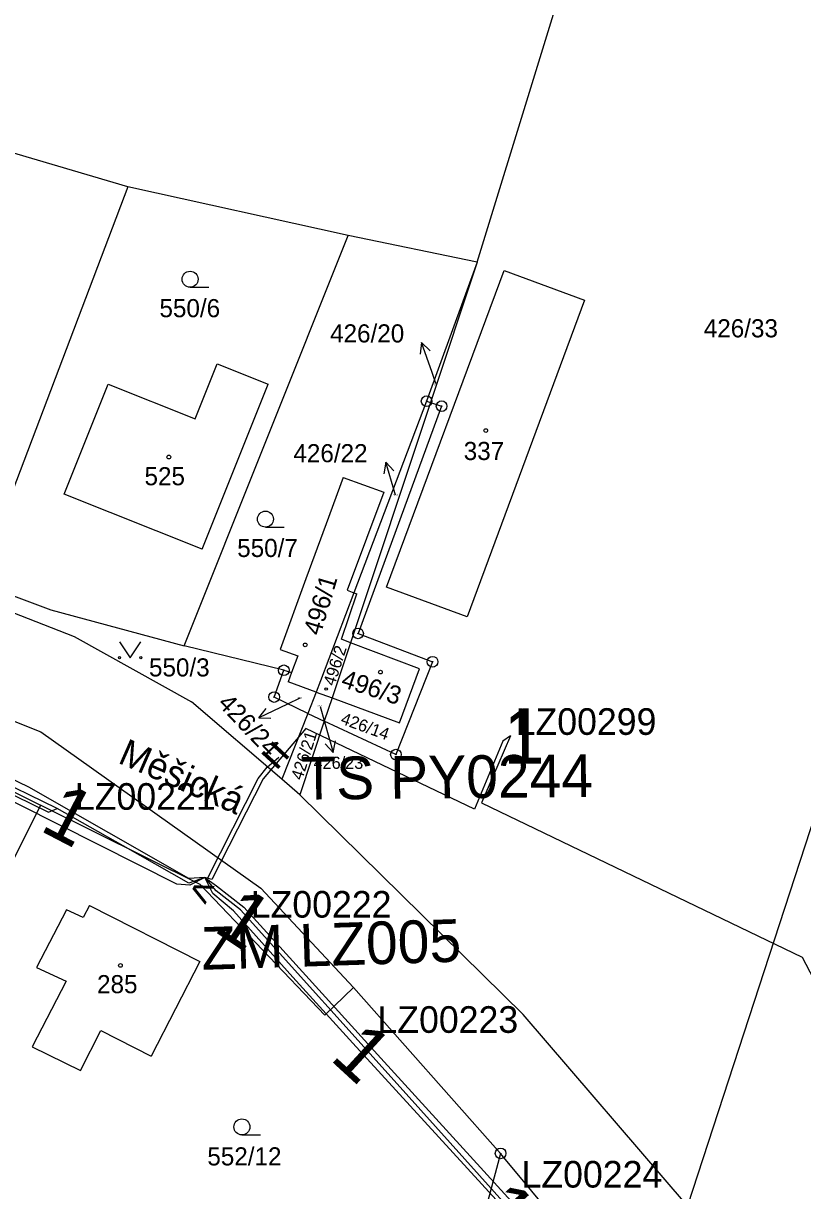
# Model space of a CAD drawing. Extents: x -738131 to -734179, y -1033447 to -1030078.
# Drawn here: x -735722 to -735648.9, y -1031900.8 to -1031791.3 of the extents above; entities that cross this region are included whole.
import ezdxf

# ---------------------------------------------------------------- set-up
doc = ezdxf.new("R2010")
doc.units = 0
for name, color, linetype in [('ftf_2010', 7, 'Continuous'), ('ftf_2060', 7, 'Continuous'), ('ftf_3010', 7, 'Continuous'), ('ftf_3010_ftf_3010_gtda_3015_gtda_3015_1', 7, 'Continuous'), ('ftf_3150', 7, 'Continuous'), ('ftf_3150_ftf_3150_gtda_3155_gtda_3155_1', 7, 'Continuous'), ('ftf_3160', 7, 'Continuous'), ('ftf_3160_ftf_3160_gtda_3165_gtda_3165_1', 7, 'Continuous'), ('ftf_nu', 7, 'Continuous'), ('Vrstva 1', 7, 'Continuous'), ('Vrstva 2', 7, 'Continuous'), ('Vrstva 3', 7, 'Continuous'), ('Vrstva 5', 7, 'Continuous'), ('Vrstva 7', 7, 'Continuous'), ('Vrstva 8', 7, 'Continuous')]:
    doc.layers.add(name, color=color, linetype=linetype)

msp = doc.modelspace()

# ---------------------------------------------------------------- linework, layer by layer
at = {"layer": 'ftf_2010'}
for points in [[(-735704.95, -1031871.47), (-735706.47, -1031871.55), (-735713.97, -1031867.28), (-735721.47, -1031863), (-735735.75, -1031856.08), (-735750.03, -1031849.16), (-735751.26, -1031849.34), (-735759.78, -1031845.67), (-735767.94, -1031842.11), (-735768.8, -1031841.74), (-735782.82, -1031840.2), (-735802.7, -1031839.67), (-735840.4, -1031839.84), (-735851.45, -1031845.21), (-735851.86, -1031848.34)], [(-735767.65, -1031843.06), (-735750.47, -1031850.23), (-735719.61, -1031865.34), (-735718.8, -1031864.98)], [(-735704.95, -1031871.47), (-735706.37, -1031872.19), (-735707.6, -1031872.09), (-735722.28, -1031864.67), (-735736.96, -1031857.25), (-735750.81, -1031850.37), (-735752.37, -1031850.93), (-735752.89, -1031850.37), (-735752.83, -1031849.61), (-735766.65, -1031843.74), (-735764.94, -1031846.69), (-735783.41, -1031916.56), (-735791.12, -1031947.31)], [(-735718.8, -1031864.98), (-735738.44, -1031855.43)], [(-735676.31, -1031858.18), (-735677.01, -1031858.66), (-735679.67, -1031865.06), (-735695.5, -1031857.49), (-735699.51, -1031862.2), (-735704.31, -1031871.66), (-735704.95, -1031871.47)], [(-735676.31, -1031858.18), (-735677.49, -1031860.92), (-735679.01, -1031864.47), (-735648.94, -1031878.95), (-735643.98, -1031888.46), (-735640.63, -1031888.9), (-735640.19, -1031889.82), (-735640.21, -1031890.18), (-735639.83, -1031890.32), (-735639.52, -1031890.34), (-735631.26, -1031887.06)], [(-735704.95, -1031871.47), (-735706.46, -1031871.99), (-735712.63, -1031868.48), (-735718.8, -1031864.98)], [(-735661.74, -1031918.22), (-735675.07, -1031904.03), (-735686.1, -1031891.76), (-735701.63, -1031874.49), (-735703.91, -1031872.73), (-735704.95, -1031871.47)], [(-735702.29, -1031874.6), (-735704.22, -1031872.98), (-735704.95, -1031871.47)], [(-735704.95, -1031871.47), (-735703.88, -1031872.24), (-735701.31, -1031874.26), (-735688.46, -1031888.4), (-735675.6, -1031902.54), (-735685.91, -1031938.23), (-735694.04, -1031973.11), (-735694.47, -1031973.74)], [(-735691.1, -1031887), (-735696.7, -1031880.8), (-735702.29, -1031874.6)], [(-735677.66, -1031901.72), (-735691.1, -1031887)]]:
    msp.add_lwpolyline(points, dxfattribs=at)
at = {"layer": 'ftf_2060'}
msp.add_lwpolyline([(-735704.95, -1031871.47), (-735704.67, -1031871.48), (-735699.95, -1031862.18), (-735699.11, -1031861.1), (-735698.04, -1031860.18)], dxfattribs=at)
at = {"layer": 'Vrstva 1'}
for points in [[(-735679.43, -1031813.72), (-735657.43, -1031742.17)], [(-735712.17, -1031806.65), (-735732.96, -1031800.52)], [(-735712.17, -1031806.65), (-735726.29, -1031843.79)], [(-735691.54, -1031811.21), (-735712.17, -1031806.65)], [(-735706.89, -1031849.74), (-735691.54, -1031811.21)], [(-735679.43, -1031813.72), (-735691.54, -1031811.21)], [(-735687.93, -1031844.21), (-735676.91, -1031814.51)], [(-735679.43, -1031813.72), (-735684.17, -1031826.77)], [(-735679.43, -1031813.72), (-735683.81, -1031826.89)], [(-735676.91, -1031814.51), (-735669.35, -1031817.28)], [(-735631.46, -1031815.6), (-735659.7, -1031902.27)], [(-735669.35, -1031817.28), (-735680.38, -1031846.99)], [(-735705.86, -1031828.42), (-735703.81, -1031823.27)], [(-735703.81, -1031823.27), (-735699.04, -1031825.17)], [(-735718.15, -1031835.51), (-735714.02, -1031825.16)], [(-735714.02, -1031825.16), (-735705.86, -1031828.42)], [(-735705.21, -1031840.67), (-735699.04, -1031825.17)], [(-735683.81, -1031826.89), (-735691.3, -1031849.43)], [(-735684.17, -1031826.77), (-735690.98, -1031844.74)], [(-735682.76, -1031827.24), (-735690.6, -1031848.56)], [(-735684.17, -1031826.77), (-735683.81, -1031826.89)], [(-735683.81, -1031826.89), (-735682.76, -1031827.24)], [(-735759.05, -1031832.5), (-735717.21, -1031848.85)], [(-735691.99, -1031833.92), (-735693.59, -1031838.29)], [(-735691.99, -1031833.92), (-735688.17, -1031835.32)], [(-735705.21, -1031840.67), (-735718.15, -1031835.51)], [(-735688.17, -1031835.32), (-735689.8, -1031839.67)], [(-735693.59, -1031838.29), (-735695.49, -1031843.45)], [(-735689.8, -1031839.67), (-735691.61, -1031844.5)], [(-735762.15, -1031841.1), (-735720.34, -1031857.78)], [(-735726.29, -1031843.79), (-735719.39, -1031846.35)], [(-735695.49, -1031843.45), (-735697.91, -1031850.06)], [(-735680.38, -1031846.99), (-735687.93, -1031844.21)], [(-735690.98, -1031844.74), (-735694.11, -1031853.01)], [(-735692.14, -1031849.11), (-735690.71, -1031844.84)], [(-735691.61, -1031844.5), (-735690.98, -1031844.74)], [(-735690.98, -1031844.74), (-735690.71, -1031844.84)], [(-735719.39, -1031846.35), (-735706.89, -1031849.74)], [(-735690.6, -1031848.56), (-735683.61, -1031851.22)], [(-735717.21, -1031848.85), (-735706.22, -1031854.97)], [(-735697.56, -1031852.02), (-735706.89, -1031849.74)], [(-735691.3, -1031849.43), (-735693.03, -1031854.62)], [(-735691.3, -1031849.43), (-735692.14, -1031849.11)], [(-735684.85, -1031851.89), (-735691.3, -1031849.43)], [(-735697.91, -1031850.06), (-735696.25, -1031850.66)], [(-735696.25, -1031850.66), (-735696.83, -1031852.23)], [(-735683.61, -1031851.22), (-735687.04, -1031859.93)], [(-735686.72, -1031856.96), (-735684.85, -1031851.89)], [(-735698.46, -1031854.53), (-735697.56, -1031852.02)], [(-735697.56, -1031852.02), (-735696.83, -1031852.23)], [(-735696.83, -1031852.23), (-735697.14, -1031853.09)], [(-735694.11, -1031853.01), (-735694.52, -1031854.06)], [(-735694.52, -1031854.06), (-735697.14, -1031853.09)], [(-735694.52, -1031854.06), (-735695.32, -1031856.08)], [(-735694.52, -1031854.06), (-735693.03, -1031854.62)], [(-735741.08, -1031854.36), (-735720.37, -1031864.67)], [(-735697.76, -1031862.24), (-735706.22, -1031854.97)], [(-735695.32, -1031856.08), (-735698.46, -1031854.53)], [(-735693.03, -1031854.62), (-735693.76, -1031856.81)], [(-735693.03, -1031854.62), (-735686.72, -1031856.96)], [(-735695.32, -1031856.08), (-735697.76, -1031862.24)], [(-735695.32, -1031856.08), (-735693.76, -1031856.81)], [(-735693.76, -1031856.81), (-735696.05, -1031863.71)], [(-735687.04, -1031859.93), (-735693.76, -1031856.81)], [(-735720.34, -1031857.78), (-735699.72, -1031872.45)], [(-735696.05, -1031863.71), (-735697.76, -1031862.24)], [(-735696.05, -1031863.71), (-735675.11, -1031884.31)], [(-735720.37, -1031864.67), (-735734.46, -1031892.93)], [(-735705.4, -1031872.12), (-735720.37, -1031864.67)], [(-735705.4, -1031872.12), (-735693.72, -1031884.37)], [(-735691.02, -1031881.79), (-735699.72, -1031872.45)], [(-735717.94, -1031874.5), (-735720.74, -1031879.92)], [(-735716.37, -1031875.21), (-735717.94, -1031874.5)], [(-735715.78, -1031874.08), (-735716.37, -1031875.21)], [(-735715.78, -1031874.08), (-735705.42, -1031879.33)], [(-735720.74, -1031879.92), (-735717.97, -1031881.19)], [(-735705.42, -1031879.33), (-735710.01, -1031888.24)], [(-735717.97, -1031881.19), (-735721.16, -1031887.36)], [(-735693.72, -1031884.37), (-735691.02, -1031881.79)], [(-735677.23, -1031897.35), (-735691.02, -1031881.79)], [(-735659.7, -1031902.27), (-735675.11, -1031884.31)], [(-735716.62, -1031889.56), (-735714.73, -1031885.82)], [(-735714.73, -1031885.82), (-735710.01, -1031888.24)], [(-735721.16, -1031887.36), (-735716.62, -1031889.56)], [(-735677.23, -1031897.35), (-735682.83, -1031918.31)], [(-735671.35, -1031904.42), (-735677.23, -1031897.35)]]:
    msp.add_lwpolyline(points, dxfattribs=at)
at = {"layer": 'Vrstva 3'}
for p, q in [((-735706.35, -1031816.08), (-735704.6, -1031816.08)), ((-735699.28, -1031838.59), (-735697.53, -1031838.59)), ((-735701.49, -1031895.62), (-735699.74, -1031895.62))]:
    msp.add_line(p, q, dxfattribs=at)
msp.add_lwpolyline([(-735712.96, -1031849.34), (-735711.96, -1031850.84), (-735710.96, -1031849.34)], dxfattribs=at)
for centre, radius in [((-735706.35, -1031815.33), 0.75), ((-735699.28, -1031837.84), 0.75), ((-735712.96, -1031850.84), 0.1), ((-735710.96, -1031850.84), 0.1), ((-735701.49, -1031894.87), 0.75)]:
    msp.add_circle(centre, radius, dxfattribs=at)
at = {"layer": 'Vrstva 5'}
for centre, radius in [((-735678.62, -1031829.53), 0.175), ((-735708.34, -1031832.01), 0.175), ((-735695.55, -1031849.64), 0.175), ((-735688.5, -1031852.19), 0.175), ((-735693.59, -1031853.78), 0.117), ((-735712.88, -1031879.71), 0.175)]:
    msp.add_circle(centre, radius, dxfattribs=at)
at = {"layer": 'Vrstva 7'}
for p, q in [((-735684.64, -1031821.26), (-735684.78, -1031822.36)), ((-735683.65, -1031824.09), (-735684.64, -1031821.26)), ((-735684.64, -1031821.26), (-735683.84, -1031822.04)), ((-735688, -1031832.5), (-735688.19, -1031833.6)), ((-735687.14, -1031835.38), (-735688, -1031832.5)), ((-735688, -1031832.5), (-735687.23, -1031833.32)), ((-735697.2, -1031855.19), (-735699.91, -1031856.49)), ((-735699.91, -1031856.49), (-735699.22, -1031855.6)), ((-735699.91, -1031856.49), (-735698.79, -1031856.51)), ((-735693.75, -1031856.86), (-735692.93, -1031859.75)), ((-735692.93, -1031859.75), (-735693.69, -1031858.92)), ((-735692.93, -1031859.75), (-735692.72, -1031858.65))]:
    msp.add_line(p, q, dxfattribs=at)
for points in [[(-735683.3, -1031825.1), (-735683.65, -1031824.09)], [(-735687.08, -1031835.59), (-735687.14, -1031835.38)], [(-735696.05, -1031854.64), (-735697.2, -1031855.19)], [(-735694.16, -1031855.41), (-735693.75, -1031856.86)]]:
    msp.add_lwpolyline(points, dxfattribs=at)
at = {"layer": 'Vrstva 8'}
for centre, radius in [((-735684.17, -1031826.77), 0.5), ((-735684.17, -1031826.77), 0.0303), ((-735682.76, -1031827.24), 0.5), ((-735682.76, -1031827.24), 0.0303), ((-735690.6, -1031848.56), 0.5), ((-735690.6, -1031848.56), 0.0303), ((-735683.61, -1031851.22), 0.5), ((-735697.56, -1031852.02), 0.5), ((-735683.61, -1031851.22), 0.0303), ((-735697.56, -1031852.02), 0.0303), ((-735698.46, -1031854.53), 0.5), ((-735698.46, -1031854.53), 0.0303), ((-735687.04, -1031859.93), 0.5), ((-735687.04, -1031859.93), 0.0303), ((-735677.23, -1031897.35), 0.5), ((-735677.23, -1031897.35), 0.0303)]:
    msp.add_circle(centre, radius, dxfattribs=at)

# ---------------------------------------------------------------- texts
at = {"layer": 'ftf_3010'}
msp.add_text('1', height=5.2, dxfattribs=at).set_placement((-735676.96, -1031860.78))
for rotation, p in [(332.5, (-735720.57, -1031866.99)), (326.2049, (-735704.28, -1031876.4)), (317.4007, (-735693.34, -1031888.48)), (311.7487, (-735680.03, -1031902.97))]:
    msp.add_text('1', height=5.2, rotation=rotation, dxfattribs=at).set_placement(p)
at = {"layer": 'ftf_3010_ftf_3010_gtda_3015_gtda_3015_1'}
for s, p in [('LZ00299', (-735675.82, -1031858.08)), ('LZ00221', (-735717.15, -1031865.11)), ('LZ00222', (-735700.66, -1031875.23)), ('LZ00223', (-735688.78, -1031886.04)), ('LZ00224', (-735675.27, -1031900.56))]:
    msp.add_text(s, height=2.5, dxfattribs=at).set_placement(p)
at = {"layer": 'ftf_3150'}
msp.add_text('>', height=2.7, rotation=153.4243, dxfattribs=at).set_placement((-735703.74, -1031872.07))
at = {"layer": 'ftf_3150_ftf_3150_gtda_3155_gtda_3155_1'}
msp.add_text('ZM LZ005', height=4, rotation=1.8363, dxfattribs=at).set_placement((-735705.24, -1031880.13))
at = {"layer": 'ftf_3160'}
msp.add_text('=', height=3.3, rotation=317.34, dxfattribs=at).set_placement((-735700.37, -1031860.28))
at = {"layer": 'ftf_3160_ftf_3160_gtda_3165_gtda_3165_1'}
msp.add_text('TS PY0244', height=4, rotation=0.5522, dxfattribs=at).set_placement((-735695.9, -1031864.16))
at = {"layer": 'ftf_nu'}
msp.add_text('Měšická', height=2.5, rotation=336.3255, dxfattribs=at).set_placement((-735713.21, -1031860.67))
at = {"layer": 'Vrstva 2'}
for s, height, p in [('550/6', 1.7, (-735709.22, -1031818.89)), ('426/33', 1.7, (-735658.18, -1031820.78)), ('337', 1.7, (-735680.69, -1031832.29)), ('525', 1.7, (-735710.62, -1031834.66)), ('426/22', 0.1, (-735687.31, -1031835.59)), ('550/7', 1.7, (-735701.93, -1031841.39)), ('550/3', 1.7, (-735710.2, -1031852.6)), ('426/24', 0.1, (-735696.27, -1031854.64)), ('426/23', 0.1, (-735694.39, -1031855.41)), ('285', 1.7, (-735715.07, -1031882.32)), ('552/12', 1.7, (-735704.73, -1031898.48))]:
    msp.add_text(s, height=height, dxfattribs=at).set_placement(p)
for s, height, rotation, p in [('426/20', 0.1, 70, (-735683.38, -1031825.31)), ('496/1', 1.7, 73.439, (-735694.13, -1031848.85)), ('496/2', 1.14, 72.2041, (-735692.81, -1031853.56)), ('496/3', 1.7, 342.0956, (-735692.29, -1031853.54)), ('426/14', 1.14, 340.0674, (-735692.31, -1031857.01)), ('426/21', 1.14, 72.3667, (-735695.84, -1031862.4))]:
    msp.add_text(s, height=height, rotation=rotation, dxfattribs=at).set_placement(p)
at = {"layer": 'Vrstva 7'}
for s, height, p in [('426/20', 1.7, (-735693.22, -1031821.26)), ('426/22', 1.7, (-735696.66, -1031832.5)), ('426/23', 1.14, (-735694.77, -1031861.27))]:
    msp.add_text(s, height=height, dxfattribs=at).set_placement(p)
msp.add_text('426/24', height=1.7, rotation=313.4518, dxfattribs=at).set_placement((-735703.84, -1031855.21))

doc.saveas('drawing.dxf')
